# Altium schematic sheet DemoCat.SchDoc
size A4
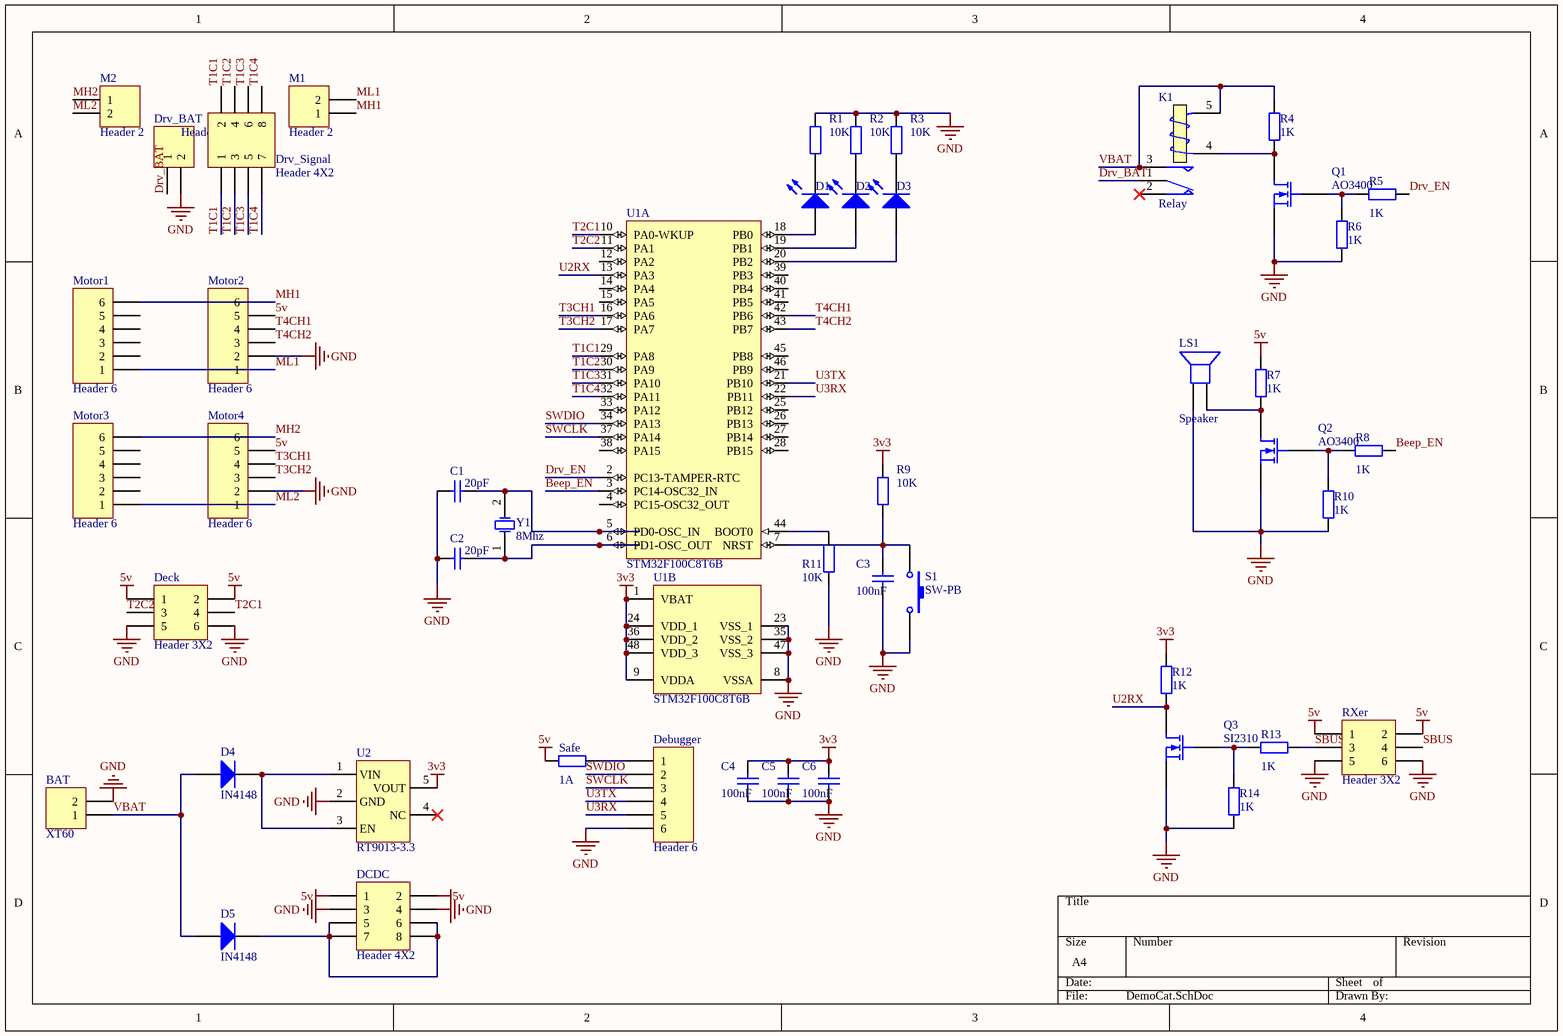
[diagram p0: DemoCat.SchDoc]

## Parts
BAT  XT60  [XT30-IN-W]
C1  value 20pF  [0603C]  (hidden comment: Cap)
C2  value 20pF  [0603C]  (hidden comment: Cap)
C3  value 100nF  [0603C]  (hidden comment: Cap)
C4  value 100nF  [0603C]  (hidden comment: Cap)
C5  value 100nF  [0603C]  (hidden comment: Cap)
C6  value 100nF  [0603C]  (hidden comment: Cap)
D1  LED0  [0603LED - Red]  (value not drawn)
D2  LED0  [0603LED - Green]  (value not drawn)
D3  LED0  [0603LED - Blue]  (value not drawn)
D4  IN4148  [DO-214AA(SMB)]
D5  IN4148  [DO-214AA(SMB)]
DCDC  Header 4X2  [HDR_SMT_2x4]
Debugger  Header 6  [GX1.25_T_6P]
Deck  Header 3X2  [HDR_SMT_2x3]
Drv_BAT  Header 2  [XH2.54_2P_T]
Drv_Signal  Header 4X2  [HDR_SMT_2x4]
K1  Relay  [rl]
LS1  Speaker  [PIN2]
M1  Header 2  [XH2.54_2P_T]
M2  Header 2  [XH2.54_2P_T]
Motor1  Header 6  [HDR_SMT_1x6]
Motor2  Header 6  [HDR_SMT_1x6]
Motor3  Header 6  [HDR_SMT_1x6]
Motor4  Header 6  [HDR_SMT_1x6]
Q1  AO3400  [SOT-23-MOS]
Q2  AO3400  [SOT-23-MOS]
Q3  SI2310  [SOT-23-MOS]
R1  10K  [0603R]
R2  10K  [0603R]
R3  10K  [0603R]
R4  value 1K  [0603R]  (hidden comment: Res2)
R5  value 1K  [0603R]  (hidden comment: Res2)
R6  value 1K  [0603R]  (hidden comment: Res2)
R7  value 1K  [0603R]  (hidden comment: Res2)
R8  value 1K  [0603R]  (hidden comment: Res2)
R9  10K  [0603R]
R10  value 1K  [0603R]  (hidden comment: Res2)
R11  value 10K  [0603R]  (hidden comment: Res2)
R12  value 1K  [0603R]  (hidden comment: Res2)
R13  value 1K  [0603R]  (hidden comment: Res2)
R14  value 1K  [0603R]  (hidden comment: Res2)
RXer  Header 3X2  [HDR_SMT_2x3]
S1  SW-PB  [KeySwitch-3X3]
Safe  value 1A  [0603R]  (hidden comment: Res2)
U1  STM32F100C8T6B  [STM-LQFP48_N]  (parts A,B of 2)
U2  RT9013-3.3  [SOT-23-5]
Y1  8Mhz  [3225-CrystalOsclitor]

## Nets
3v3: C4.2 C5.2 C6.2 R9.2 R12.2 U1.1(VBAT) U1.9(VDDA) U1.24(VDD_1) U1.36(VDD_2) U1.48(VDD_3) U2.5(VOUT)
5v: DCDC.1 DCDC.2 Deck.1 Deck.2 Motor2.5 Motor4.5 R7.2 RXer.1 RXer.2 Safe.1
GND: BAT.2 C1.1 C2.1 C3.1 C4.1 C5.1 C6.1 DCDC.3 DCDC.4 Debugger.6 Deck.5 Deck.6 Drv_BAT.2 LS1.1 Motor2.2 Motor4.2 Q1.3(S) Q2.3(S) Q3.3(S) R1.2 R2.2 R3.2 R6.1 R10.1 R11.1 R14.1 RXer.5 RXer.6 S1.2 U1.8(VSSA) U1.23(VSS_1) U1.35(VSS_2) U1.47(VSS_3) U2.2(GND)
Beep_EN: R8.2 U1.3(PC14-OSC32_IN)
Drv_BAT: Drv_BAT.1 K1.1(COM)
Drv_EN: R5.2 U1.2(PC13-TAMPER-RTC)
MH1: M1.1 Motor1.6 Motor2.6
MH2: M2.1 Motor3.6 Motor4.6
ML1: M1.2 Motor1.1 Motor2.1
ML2: M2.2 Motor3.1 Motor4.1
SBUS: R13.2 RXer.3 RXer.4
SWCLK: Debugger.3 U1.37(PA14)
SWDIO: Debugger.2 U1.34(PA13)
T1C1: Drv_Signal.1 Drv_Signal.2 U1.29(PA8)
T1C2: Drv_Signal.3 Drv_Signal.4 U1.30(PA9)
T1C3: Drv_Signal.5 Drv_Signal.6 U1.31(PA10)
T1C4: Drv_Signal.7 Drv_Signal.8 U1.32(PA11)
T2C1: Deck.4 U1.10(PA0-WKUP)
T2C2: Deck.3 U1.11(PA1)
T3CH1: Motor4.4 U1.16(PA6)
T3CH2: Motor4.3 U1.17(PA7)
T4CH1: Motor2.4 U1.42(PB6)
T4CH2: Motor2.3 U1.43(PB7)
U2RX: Q3.1(D) R12.1 U1.13(PA3)
U3RX: Debugger.5 U1.22(PB11)
U3TX: Debugger.4 U1.21(PB10)
VBAT: BAT.1 D4.1(A) D5.1(A) K1.3(NO) K1.5(T2) R4.2
NetC1_2: C1.2 U1.5(PD0-OSC_IN) Y1.2(OSC2)
NetC2_2: C2.2 U1.6(PD1-OSC_OUT) Y1.1(OSC1)
NetC3_2: C3.2 R9.1 S1.1 U1.7(NRST)
NetD1_1: D1.1(A) U1.18(PB0)
NetD1_2: D1.2(K) R1.1
NetD2_1: D2.1(A) U1.19(PB1)
NetD2_2: D2.2(K) R2.1
NetD3_1: D3.1(A) U1.20(PB2)
NetD3_2: D3.2(K) R3.1
NetD4_2: D4.2(K) U2.1(VIN) U2.3(EN)
NetD5_2: D5.2(K) DCDC.5 DCDC.6 DCDC.7 DCDC.8
NetDebugger_1: Debugger.1 Safe.2
NetK1_4: K1.4(T1) Q1.1(D) R4.1
NetLS1_2: LS1.2 Q2.1(D) R7.1
NetQ1_2: Q1.2(G) R5.1 R6.2
NetQ2_2: Q2.2(G) R8.1 R10.2
NetQ3_2: Q3.2(G) R13.1 R14.2
NetR11_2: R11.2 U1.44(BOOT0)

Not connected (* = marked no-connect by the designer): K1 2(NC)*; Motor1 2 3 4 5; Motor3 2 3 4 5; U1 4(PC15-OSC32_OUT) 12(PA2) 14(PA4) 15(PA5) 25(PB12) 26(PB13) 27(PB14) 28(PB15) 33(PA12) 38(PA15) 39(PB3) 40(PB4) 41(PB5) 45(PB8) 46(PB9); U2 4(NC)*

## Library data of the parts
BAT Drv_BAT M1 M2 = Header 2: Header, 2-Pin
C1-C6 = Cap: Capacitor
D1-D3 = LED0: Typical INFRARED GaAs LED
D4 D5 = Diode: Default Diode
DCDC Drv_Signal = Header 4X2: Header, 4-Pin, Dual row
Debugger Motor1-Motor4 = Header 6: Header, 6-Pin
Deck RXer = Header 3X2: Header, 3-Pin, Dual row
K1 = Relay: SPDT Relay
LS1 = Speaker: Loudspeaker
Q1-Q3 = MOSFET-N: N-Channel MOSFET
R1-R14 Safe = Res2: Resistor
S1 = SW-PB: Switch
U1 = STM32F100C8T6B: ARM Cortex-M3 32-bit MCU, 64 KB Flash, 8 KB Internal RAM, 37 I/Os, 48-pin LQFP, -40 to 85 degC, Tray; A/D Converter: 1x12-bit (10 Channel); D/A Converter: 2x12-bit (2 Channel); FLASH Size (Prog) (kB): 64; I/Os (High Current): 37; Internal RAM Size (kB): 8; Operating Frequency(F) (Processor speed) (MHz): 24; Supply Voltage(Vcc) min (V): 2
U2 = RT9013: 3.3V 500mA
Y1 = XTAL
